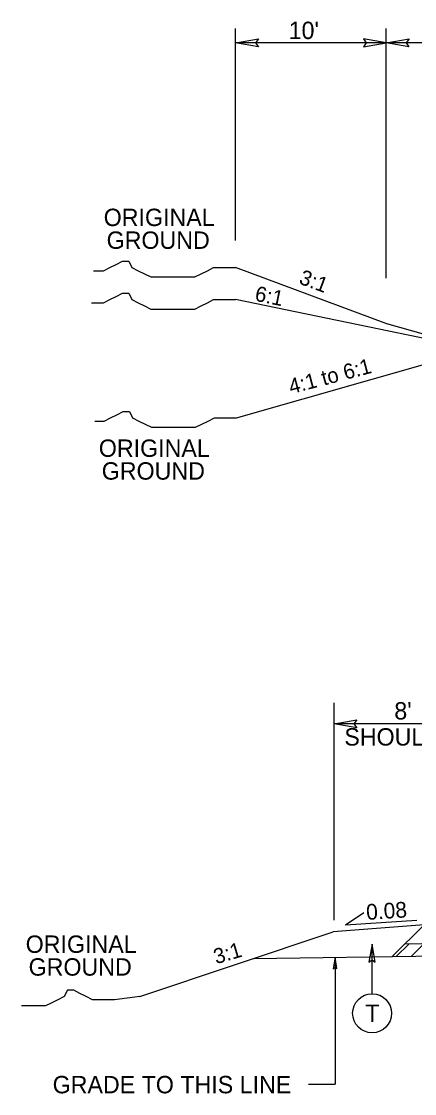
# Model space of a CAD drawing. Extents: x 2176024 to 2177225, y 75947 to 76635.
# Drawn here: x 2176163.6 to 2176189.7, y 76464.9 to 76536.1 of the extents above; entities that cross this region are included whole.
import ezdxf

# ---------------------------------------------------------------- set-up
doc = ezdxf.new("R2010")
doc.units = 0
for name, color, linetype in [('Old_Level_1', 7, 'Continuous'), ('Old_Level_11', 7, 'Continuous'), ('Prop Dimension', 7, 'Continuous'), ('Typical Curb CELL', 7, 'Continuous'), ('Typical Pavement Slope CELL', 7, 'Continuous'), ('Typical Pavement Slope Information CELL', 7, 'Continuous'), ('Typical Shoulder Slope CELL', 7, 'Continuous'), ('Typical Slope Point Local CELL', 7, 'Continuous'), ('Typical Terminator CELL', 7, 'Continuous'), ('Typical Text General CELL', 7, 'Continuous')]:
    doc.layers.add(name, color=color, linetype=linetype)

msp = doc.modelspace()

# ---------------------------------------------------------------- linework, layer by layer
at = {"layer": 'Old_Level_1'}
for p, q in [((2176188.529, 76474.041), (2176189.343, 76474.839)), ((2176189.518, 76474.041), (2176190.345, 76474.851))]:
    msp.add_line(p, q, dxfattribs=at)
at = {"layer": 'Old_Level_11'}
msp.add_line((2176186.908, 76471.538), (2176186.908, 76474.834), dxfattribs=at)
msp.add_lwpolyline([(2176187.115, 76473.634), (2176186.908, 76474.834), (2176186.695, 76473.627), (2176186.908, 76473.78)], close=True, dxfattribs=at)
msp.add_circle((2176186.908, 76470.242), 1.296, dxfattribs=at)
at = {"layer": 'Prop Dimension'}
for p, q in [((2176177.841, 76521.53), (2176177.841, 76535.602)), ((2176187.841, 76519.025), (2176187.841, 76535.602)), ((2176187.841, 76534.648), (2176177.841, 76534.648)), ((2176193.841, 76534.648), (2176187.841, 76534.648)), ((2176184.375, 76476.417), (2176184.375, 76490.847)), ((2176194.375, 76489.451), (2176184.375, 76489.451)), ((2176184.442, 76473.96), (2176184.442, 76465.534)), ((2176182.675, 76465.534), (2176184.442, 76465.534))]:
    msp.add_line(p, q, dxfattribs=at)
at = {"layer": 'Typical Curb CELL'}
msp.add_line((2176179.051, 76473.88), (2176199.455, 76474.183), dxfattribs=at)
at = {"layer": 'Typical Pavement Slope CELL'}
for p, q in [((2176193.841, 76514.314), (2176177.841, 76517.609)), ((2176190.362, 76476.121), (2176188.246, 76474.016)), ((2176199.443, 76474.989), (2176189.069, 76474.835))]:
    msp.add_line(p, q, dxfattribs=at)
at = {"layer": 'Typical Pavement Slope Information CELL'}
for q in [(2176186.359, 76476.923), (2176189.88, 76476.417)]:
    msp.add_line((2176185.134, 76476.104), q, dxfattribs=at)
at = {"layer": 'Typical Shoulder Slope CELL'}
for p, q in [((2176187.894, 76516.012), (2176177.841, 76519.737)), ((2176177.887, 76509.758), (2176209.86, 76518.888)), ((2176193.841, 76514.314), (2176187.894, 76516.012)), ((2176190.362, 76476.121), (2176184.327, 76475.638)), ((2176171.468, 76471.352), (2176184.327, 76475.638))]:
    msp.add_line(p, q, dxfattribs=at)
at = {"layer": 'Typical Slope Point Local CELL'}
for points in [[(2176168.406, 76519.529), (2176168.651, 76519.529), (2176169.068, 76519.529), (2176169.486, 76519.737), (2176169.904, 76519.947), (2176170.321, 76520.157), (2176170.739, 76520.157), (2176170.949, 76519.737), (2176171.366, 76519.529), (2176171.784, 76519.32), (2176172.202, 76519.112), (2176172.619, 76519.112), (2176173.037, 76519.112), (2176173.455, 76519.112), (2176173.872, 76519.112), (2176174.29, 76519.112), (2176174.708, 76519.112), (2176175.125, 76519.112), (2176175.543, 76519.32), (2176175.96, 76519.529), (2176176.378, 76519.737), (2176177.005, 76519.737), (2176177.423, 76519.737), (2176177.841, 76519.737)], [(2176168.273, 76517.401), (2176168.651, 76517.401), (2176169.068, 76517.401), (2176169.486, 76517.609), (2176169.904, 76517.818), (2176170.321, 76518.028), (2176170.739, 76518.028), (2176170.949, 76517.609), (2176171.366, 76517.401), (2176171.784, 76517.191), (2176172.202, 76516.983), (2176172.619, 76516.983), (2176173.037, 76516.983), (2176173.455, 76516.983), (2176173.872, 76516.983), (2176174.29, 76516.983), (2176174.708, 76516.983), (2176175.125, 76516.983), (2176175.543, 76517.191), (2176175.96, 76517.401), (2176176.378, 76517.609), (2176177.005, 76517.609), (2176177.423, 76517.609), (2176177.841, 76517.609)], [(2176168.497, 76509.55), (2176168.697, 76509.55), (2176169.115, 76509.55), (2176169.533, 76509.758), (2176169.95, 76509.968), (2176170.368, 76510.178), (2176170.786, 76510.178), (2176170.995, 76509.758), (2176171.413, 76509.55), (2176171.831, 76509.341), (2176172.248, 76509.133), (2176172.666, 76509.133), (2176173.084, 76509.133), (2176173.501, 76509.133), (2176173.919, 76509.133), (2176174.337, 76509.133), (2176174.754, 76509.133), (2176175.172, 76509.133), (2176175.589, 76509.341), (2176176.007, 76509.55), (2176176.425, 76509.758), (2176177.052, 76509.758), (2176177.47, 76509.758), (2176177.887, 76509.758)], [(2176171.468, 76471.352), (2176169.798, 76471.144), (2176169.38, 76471.144), (2176168.753, 76471.144), (2176168.335, 76471.144), (2176167.917, 76471.352), (2176167.5, 76471.561), (2176167.082, 76471.771), (2176166.664, 76471.771), (2176166.455, 76471.352), (2176166.037, 76471.144), (2176165.619, 76470.934), (2176165.202, 76470.726), (2176164.784, 76470.726), (2176164.366, 76470.726), (2176163.949, 76470.726), (2176163.609, 76470.726)]]:
    msp.add_lwpolyline(points, dxfattribs=at)
at = {"layer": 'Typical Terminator CELL'}
for points in [[(2176179.35, 76534.388), (2176177.841, 76534.648), (2176179.359, 76534.917), (2176179.166, 76534.648)], [(2176186.331, 76534.388), (2176187.841, 76534.648), (2176186.323, 76534.917), (2176186.516, 76534.648)], [(2176189.35, 76534.388), (2176187.841, 76534.648), (2176189.359, 76534.917), (2176189.166, 76534.648)], [(2176185.884, 76489.191), (2176184.375, 76489.451), (2176185.893, 76489.72), (2176185.7, 76489.451)], [(2176184.572, 76473.205), (2176184.442, 76473.96), (2176184.308, 76473.201), (2176184.442, 76473.297)]]:
    msp.add_lwpolyline(points, close=True, dxfattribs=at)

# ---------------------------------------------------------------- texts
at = {"layer": 'Old_Level_11'}
msp.add_text('T', height=1.16, rotation=359.99974, dxfattribs=at).set_placement((2176186.451, 76469.662))
at = {"layer": 'Typical Pavement Slope Information CELL'}
msp.add_text('0.08', height=1.0429, rotation=3.78012, dxfattribs=at).set_placement((2176186.544, 76476.434))
at = {"layer": 'Typical Slope Point Local CELL'}
for s, rotation, p in [('3:1', 339.63369, (2176181.988, 76518.69)), ('6:1', 348.41207, (2176179.062, 76517.544)), ('4:1 to 6:1', 14.73365, (2176181.516, 76511.33)), ('3:1', 16.46494, (2176176.545, 76473.491))]:
    msp.add_text(s, height=1.0064, rotation=rotation, dxfattribs=at).set_placement(p)
at = {"layer": 'Typical Text General CELL'}
for s, height, p in [("10'", 1.1533, (2176181.362, 76534.901)), ('ORIGINAL', 1.1533, (2176169.075, 76522.49)), ('GROUND', 1.1533, (2176169.269, 76520.978)), ('ORIGINAL', 1.1533, (2176168.752, 76507.172)), ('GROUND', 1.1533, (2176168.945, 76505.66)), ("8'", 1.1533, (2176188.38, 76489.74)), ('SHOULDER', 1.1533, (2176185.061, 76488.01)), ('ORIGINAL', 1.1533, (2176163.893, 76474.252)), ('GROUND', 1.1533, (2176164.087, 76472.74)), ('GRADE TO THIS LINE', 1.15334, (2176165.683, 76464.93))]:
    msp.add_text(s, height=height, dxfattribs=at).set_placement(p)

doc.saveas('drawing.dxf')
